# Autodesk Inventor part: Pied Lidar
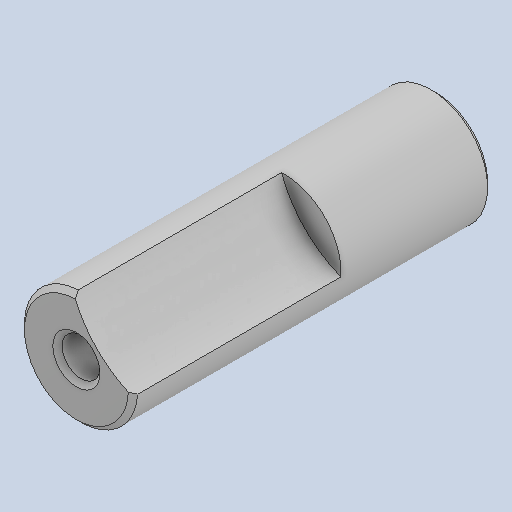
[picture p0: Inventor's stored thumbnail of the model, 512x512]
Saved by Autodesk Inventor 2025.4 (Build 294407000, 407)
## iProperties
Created: 2026-06
Part Number: Pied Lidar
Material: Generic
Document SubType Name: Modeling
Designer: AdminForWorker
Density: 1 g/cm^3
Appearance: Default
Title: Pied Lidar v4
Author: AdminForWorker
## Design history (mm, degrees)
feature "pied_lidar"
body "Solid1"
